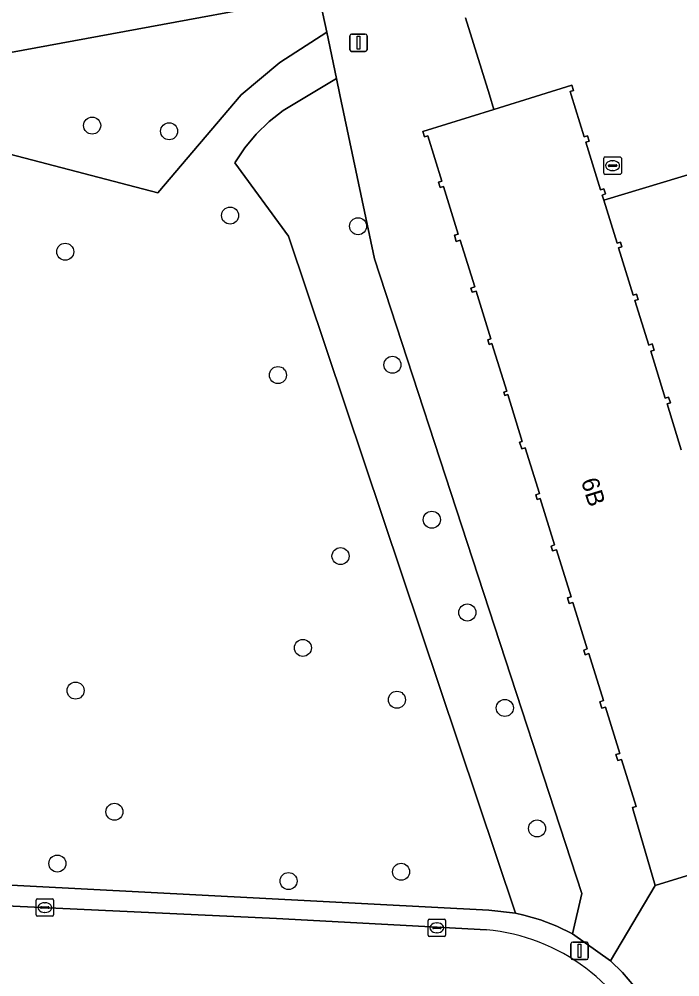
# Model space of a CAD drawing. Extents: x 161248 to 161848, y 384871 to 385383.
# Drawn here: x 161411.8 to 161449.7, y 384949.3 to 385004.4 of the extents above; entities that cross this region are included whole.
import ezdxf

# ---------------------------------------------------------------- set-up
doc = ezdxf.new("R2010")
doc.units = 0
for name, color, linetype in [('IMGEO_Boom', 7, 'Continuous'), ('IMGEO_Erf', 7, 'Continuous'), ('IMGEO_Groenvoorziening', 7, 'Continuous'), ('IMGEO_Hek', 7, 'Continuous'), ('IMGEO_Kolk', 7, 'Continuous'), ('IMGEO_Lichtmast', 7, 'Continuous'), ('IMGEO_Pand', 7, 'Continuous'), ('IMGEO_Pand_nummerreeks', 7, 'Continuous'), ('IMGEO_Rijbaan_lokaal_open', 7, 'Continuous'), ('IMGEO_Rioolput', 7, 'Continuous'), ('IMGEO_Voetpad_open', 7, 'Continuous')]:
    doc.layers.add(name, color=color, linetype=linetype)

msp = doc.modelspace()

# ---------------------------------------------------------------- linework, layer by layer
at = {"layer": 'IMGEO_Boom'}
for centre in [(161415.979, 384998.236), (161420.399, 384997.91), (161423.899, 384993.064), (161431.249, 384992.453), (161414.431, 384990.989), (161433.223, 384984.489), (161426.651, 384983.899), (161435.488, 384975.586), (161430.243, 384973.495), (161437.527, 384970.251), (161428.081, 384968.214), (161415.029, 384965.761), (161433.486, 384965.238), (161439.681, 384964.763), (161417.258, 384958.8), (161441.529, 384957.841), (161413.98, 384955.819), (161433.72, 384955.346), (161427.258, 384954.817)]:
    msp.add_circle(centre, 0.489, dxfattribs=at)
at = {"layer": 'IMGEO_Erf'}
msp.add_lwpolyline([(161417, 385055.584), (161373.417, 385041.421), (161374.342, 385036.357), (161375.419, 385030.464), (161376.296, 385025.659), (161377.093, 385021.299), (161377.39, 385019.671), (161380.984, 385000), (161381.538, 384996.968), (161428.963, 385005.723), (161422.894, 385029.848), (161421.184, 385036.607), (161421.765, 385036.754)], close=True, dxfattribs=at)
msp.add_lwpolyline([(161429.001, 385005.73), (161429.448, 385003.612), (161430.009, 385000.952), (161430.209, 385000), (161432.194, 384990.572), (161444.094, 384954.097), (161443.567, 384951.787), (161445.755, 384950.228), (161448.319, 384954.566), (161447.068, 384958.835), (161447.004, 384959.044), (161447.214, 384959.109), (161446.379, 384961.802), (161446.171, 384961.737), (161446.063, 384962.086), (161446.283, 384962.154), (161445.458, 384964.813), (161445.252, 384964.749), (161445.135, 384965.125), (161445.344, 384965.19), (161444.507, 384967.888), (161444.298, 384967.824), (161444.214, 384968.094), (161444.416, 384968.157), (161443.588, 384970.826), (161443.38, 384970.762), (161443.279, 384971.086), (161443.488, 384971.151), (161442.648, 384973.858), (161442.423, 384973.789), (161442.337, 384974.068), (161442.538, 384974.131), (161441.709, 384976.801), (161441.538, 384976.748), (161441.453, 384977.019), (161441.665, 384977.085), (161440.848, 384979.718), (161440.649, 384979.656), (161440.53, 384980.038), (161440.684, 384980.086), (161439.847, 384982.78), (161439.683, 384982.729), (161439.623, 384982.922), (161439.788, 384982.974), (161438.941, 384985.704), (161438.78, 384985.654), (161438.696, 384985.924), (161438.88, 384985.981), (161438.029, 384988.724), (161437.809, 384988.656), (161437.735, 384988.893), (161437.951, 384988.96), (161437.116, 384991.649), (161436.892, 384991.579), (161436.781, 384991.936), (161437.006, 384992.006), (161436.159, 384994.739), (161435.967, 384994.68), (161435.873, 384994.985), (161436.064, 384995.044), (161435.254, 384997.653), (161435.064, 384997.593), (161434.969, 384997.898), (161439.058, 384999.168), (161438.8, 385000), (161437.426, 385004.427)], dxfattribs=at)
at = {"layer": 'IMGEO_Groenvoorziening'}
for points in [[(161424.534, 385000), (161426.767, 385001.869), (161429.448, 385003.612), (161429.001, 385005.73), (161428.963, 385005.723), (161381.538, 384996.968), (161378.531, 384996.444), (161381.658, 384978.992), (161385.169, 384955.944), (161385.699, 384955.916), (161382.254, 384992.314), (161382.704, 384992.395), (161409.099, 384997.144), (161419.747, 384994.367)], [(161426.767, 385001.869), (161424.534, 385000), (161419.747, 384994.367), (161409.099, 384997.144), (161382.704, 384992.395), (161382.254, 384992.314), (161385.699, 384955.916), (161438.755, 384953.144), (161440.288, 384952.96), (161427.248, 384991.885), (161424.179, 384996.091), (161424.75, 384996.95), (161425.408, 384997.745), (161426.145, 384998.467), (161426.954, 384999.107), (161430.009, 385000.952), (161429.448, 385003.612)], [(161443.567, 384951.787), (161444.094, 384954.097), (161432.194, 384990.572), (161430.209, 385000), (161430.009, 385000.952), (161426.954, 384999.107), (161426.145, 384998.467), (161425.408, 384997.745), (161424.75, 384996.95), (161424.179, 384996.091), (161427.248, 384991.885), (161440.288, 384952.96), (161440.771, 384952.857), (161441.734, 384952.584), (161442.668, 384952.227)], [(161456.306, 384927.519), (161456.058, 384928.282), (161468.671, 384932.496), (161460.725, 384958.4), (161453.097, 384956.043), (161448.319, 384954.566), (161445.755, 384950.228), (161446.432, 384949.557), (161447.081, 384948.789), (161447.66, 384947.966), (161448.163, 384947.095), (161448.585, 384946.183), (161448.925, 384945.236), (161454.217, 384928.071), (161455.63, 384928.386), (161455.957, 384927.409)]]:
    msp.add_lwpolyline(points, close=True, dxfattribs=at)
at = {"layer": 'IMGEO_Hek'}
msp.add_lwpolyline([(161452.034, 384995.958), (161445.368, 384993.944)], dxfattribs=at)
at = {"layer": 'IMGEO_Kolk'}
for p, q in [((161412.759, 384952.865), (161412.759, 384953.717)), ((161412.834, 384953.791), (161413.686, 384953.791)), ((161413.76, 384953.717), (161413.76, 384952.865)), ((161413.018, 384953.285), (161413.018, 384953.297)), ((161413.456, 384953.248), (161413.058, 384953.248)), ((161413.061, 384953.334), (161413.459, 384953.334)), ((161413.247, 384953.571), (161413.272, 384953.571)), ((161413.502, 384953.297), (161413.502, 384953.285)), ((161413.686, 384952.791), (161412.834, 384952.791)), ((161413.27, 384953.011), (161413.245, 384953.011)), ((161435.352, 384952.625), (161436.204, 384952.625)), ((161435.277, 384951.699), (161435.277, 384952.551)), ((161435.536, 384952.119), (161435.536, 384952.131)), ((161435.974, 384952.082), (161435.576, 384952.082)), ((161435.579, 384952.168), (161435.977, 384952.168)), ((161435.765, 384952.405), (161435.79, 384952.405)), ((161436.02, 384952.131), (161436.02, 384952.119)), ((161436.278, 384952.551), (161436.278, 384951.699)), ((161436.204, 384951.625), (161435.352, 384951.625)), ((161435.788, 384951.845), (161435.763, 384951.845))]:
    msp.add_line(p, q, dxfattribs=at)
for points in [[(161412.759, 384952.865), (161412.759, 384953.717)], [(161412.834, 384953.791), (161413.686, 384953.791)], [(161413.76, 384953.717), (161413.76, 384952.865)], [(161413.686, 384952.791), (161412.834, 384952.791)], [(161435.352, 384952.625), (161436.204, 384952.625)], [(161435.277, 384951.699), (161435.277, 384952.551)], [(161436.278, 384952.551), (161436.278, 384951.699)], [(161436.204, 384951.625), (161435.352, 384951.625)]]:
    msp.add_lwpolyline(points, dxfattribs=at)
for centre, radius, start, end in [((161412.836, 384953.715), 0.0765, 91.552, 178.448), ((161412.836, 384953.715), 0.0765, 91.552, 178.448), ((161413.684, 384953.715), 0.0765, 1.552, 88.448), ((161413.684, 384953.715), 0.0765, 1.552, 88.448), ((161413.058, 384953.294), 0.0403, 85.8775, 175.7526), ((161413.055, 384953.284), 0.0366, 178.938, 274.7102), ((161413.459, 384953.291), 0.043, 264.8664, 352.4533), ((161413.463, 384953.296), 0.0386, 1.7309, 96.639), ((161412.836, 384952.867), 0.0765, 181.552, 268.448), ((161412.836, 384952.867), 0.0765, 181.552, 268.448), ((161413.684, 384952.867), 0.0765, 271.552, 358.448), ((161413.684, 384952.867), 0.0765, 271.552, 358.448), ((161435.354, 384952.549), 0.0765, 91.552, 178.448), ((161435.354, 384952.549), 0.0765, 91.552, 178.448), ((161436.202, 384952.549), 0.0765, 1.552, 88.448), ((161436.202, 384952.549), 0.0765, 1.552, 88.448), ((161435.576, 384952.128), 0.0403, 85.8775, 175.7526), ((161435.573, 384952.118), 0.0366, 178.938, 274.7102), ((161435.977, 384952.125), 0.043, 264.8664, 352.4533), ((161435.981, 384952.13), 0.0386, 1.7309, 96.639), ((161435.354, 384951.701), 0.0765, 181.552, 268.448), ((161435.354, 384951.701), 0.0765, 181.552, 268.448), ((161436.202, 384951.701), 0.0765, 271.552, 358.448), ((161436.202, 384951.701), 0.0765, 271.552, 358.448)]:
    msp.add_arc(centre, radius, start, end, dxfattribs=at)
for centre, major_axis, ratio, start_param, end_param in [((161413.246, 384953.291), (-0.387, 0.002), 0.722429, 4.712389, 7.853982), ((161413.271, 384953.291), (-0.39, 0.002), 0.717154, 1.570796, 4.712389), ((161435.764, 384952.125), (-0.387, 0.002), 0.722429, 4.712389, 7.853982), ((161435.789, 384952.125), (-0.39, 0.002), 0.717154, 1.570796, 4.712389)]:
    msp.add_ellipse(centre, major_axis=major_axis, ratio=ratio, start_param=start_param, end_param=end_param, dxfattribs=at)
at = {"layer": 'IMGEO_Lichtmast'}
for p, q in [((161430.778, 385002.598), (161430.778, 385003.398)), ((161430.778, 385003.398), (161430.778, 385002.598)), ((161430.878, 385003.498), (161431.668, 385003.498)), ((161431.668, 385003.498), (161430.878, 385003.498)), ((161431.768, 385003.398), (161431.768, 385002.598)), ((161431.768, 385002.598), (161431.768, 385003.398)), ((161431.668, 385002.498), (161430.878, 385002.498)), ((161430.878, 385002.498), (161431.668, 385002.498)), ((161443.48, 384950.404), (161443.48, 384951.204)), ((161443.48, 384951.204), (161443.48, 384950.404)), ((161443.58, 384951.304), (161444.37, 384951.304)), ((161444.37, 384951.304), (161443.58, 384951.304)), ((161444.47, 384951.204), (161444.47, 384950.404)), ((161444.47, 384950.404), (161444.47, 384951.204)), ((161444.37, 384950.304), (161443.58, 384950.304)), ((161443.58, 384950.304), (161444.37, 384950.304))]:
    msp.add_line(p, q, dxfattribs=at)
for points in [[(161431.198, 385003.373), (161431.348, 385003.373), (161431.348, 385002.623), (161431.198, 385002.623), (161431.198, 385003.373)], [(161443.9, 384951.179), (161444.05, 384951.179), (161444.05, 384950.429), (161443.9, 384950.429), (161443.9, 384951.179)]]:
    msp.add_lwpolyline(points, dxfattribs=at)
for centre, start, end in [((161430.878, 385003.398), 90, 180), ((161430.878, 385003.398), 90, 180), ((161431.668, 385003.398), 0, 90), ((161431.668, 385003.398), 360, 90), ((161430.878, 385002.598), 180, 270), ((161430.878, 385002.598), 180, 270), ((161431.668, 385002.598), 270, 0), ((161431.668, 385002.598), 270, 0), ((161443.58, 384951.204), 90, 180), ((161443.58, 384951.204), 90, 180), ((161444.37, 384951.204), 0, 90), ((161444.37, 384951.204), 360, 90), ((161443.58, 384950.404), 180, 270), ((161443.58, 384950.404), 180, 270), ((161444.37, 384950.404), 270, 0), ((161444.37, 384950.404), 270, 0)]:
    msp.add_arc(centre, 0.1, start, end, dxfattribs=at)
at = {"layer": 'IMGEO_Pand'}
msp.add_lwpolyline([(161449.815, 384979.605), (161448.998, 384982.236), (161449.19, 384982.296), (161449.085, 384982.632), (161448.895, 384982.573), (161448.06, 384985.263), (161448.25, 384985.323), (161448.138, 384985.684), (161447.948, 384985.625), (161447.156, 384988.179), (161447.346, 384988.238), (161447.25, 384988.547), (161447.06, 384988.488), (161446.217, 384991.205), (161446.407, 384991.266), (161446.32, 384991.544), (161446.13, 384991.487), (161445.368, 384993.944), (161445.274, 384994.246), (161445.464, 384994.309), (161445.372, 384994.603), (161445.182, 384994.544), (161444.334, 384997.277), (161444.53, 384997.338), (161444.429, 384997.642), (161444.239, 384997.582), (161443.49, 385000), (161443.431, 385000.19), (161443.622, 385000.25), (161443.527, 385000.555), (161441.739, 385000), (161439.058, 384999.168), (161434.969, 384997.898), (161435.064, 384997.593), (161435.254, 384997.653), (161436.064, 384995.044), (161435.873, 384994.985), (161435.967, 384994.68), (161436.159, 384994.739), (161437.006, 384992.006), (161436.781, 384991.936), (161436.892, 384991.579), (161437.116, 384991.649), (161437.951, 384988.96), (161437.735, 384988.893), (161437.809, 384988.656), (161438.029, 384988.724), (161438.88, 384985.981), (161438.696, 384985.924), (161438.78, 384985.654), (161438.941, 384985.704), (161439.788, 384982.974), (161439.623, 384982.922), (161439.683, 384982.729), (161439.847, 384982.78), (161440.684, 384980.086), (161440.53, 384980.038), (161440.649, 384979.656), (161440.848, 384979.718), (161441.665, 384977.085), (161441.453, 384977.019), (161441.538, 384976.748), (161441.709, 384976.801), (161442.538, 384974.131), (161442.337, 384974.068), (161442.423, 384973.789), (161442.648, 384973.858), (161443.488, 384971.151), (161443.279, 384971.086), (161443.38, 384970.762), (161443.588, 384970.826), (161444.416, 384968.157), (161444.214, 384968.094), (161444.298, 384967.824), (161444.507, 384967.888), (161445.344, 384965.19), (161445.135, 384965.125), (161445.252, 384964.749), (161445.458, 384964.813), (161446.283, 384962.154), (161446.063, 384962.086), (161446.171, 384961.737), (161446.379, 384961.802), (161447.214, 384959.109), (161447.004, 384959.044), (161447.068, 384958.835), (161448.319, 384954.566), (161453.097, 384956.043)], dxfattribs=at)
at = {"layer": 'IMGEO_Rijbaan_lokaal_open'}
for points in [[(161437.426, 385004.427), (161438.8, 385000), (161439.058, 384999.168), (161441.739, 385000), (161443.527, 385000.555), (161443.622, 385000.25), (161443.431, 385000.19), (161443.49, 385000), (161444.239, 384997.582), (161444.429, 384997.642), (161444.53, 384997.338), (161444.334, 384997.277), (161445.182, 384994.544), (161445.372, 384994.603), (161445.464, 384994.309), (161445.274, 384994.246), (161445.368, 384993.944), (161452.034, 384995.958)], [(161452.034, 384995.958), (161445.368, 384993.944), (161446.13, 384991.487), (161446.32, 384991.544), (161446.407, 384991.266), (161446.217, 384991.205), (161447.06, 384988.488), (161447.25, 384988.547), (161447.346, 384988.238), (161447.156, 384988.179), (161447.948, 384985.625), (161448.138, 384985.684), (161448.25, 384985.323), (161448.06, 384985.263), (161448.895, 384982.573), (161449.085, 384982.632), (161449.19, 384982.296), (161448.998, 384982.236), (161449.815, 384979.605)], [(161438.622, 384952.015), (161426.573, 384952.665), (161402.419, 384953.798)]]:
    msp.add_lwpolyline(points, dxfattribs=at)
msp.add_arc((161437.605, 384940.914), 11.147, 21.1103, 84.764, dxfattribs=at)
at = {"layer": 'IMGEO_Rioolput'}
for p, q in [((161445.371, 384995.508), (161445.371, 384996.36)), ((161445.446, 384996.434), (161446.298, 384996.434)), ((161445.859, 384996.214), (161445.884, 384996.214)), ((161446.372, 384996.36), (161446.372, 384995.508)), ((161445.63, 384995.928), (161445.63, 384995.94)), ((161446.068, 384995.891), (161445.67, 384995.891)), ((161445.673, 384995.977), (161446.071, 384995.977)), ((161445.882, 384995.654), (161445.857, 384995.654)), ((161446.114, 384995.94), (161446.114, 384995.928)), ((161446.298, 384995.434), (161445.446, 384995.434))]:
    msp.add_line(p, q, dxfattribs=at)
for points in [[(161445.371, 384995.508), (161445.371, 384996.36)], [(161445.446, 384996.434), (161446.298, 384996.434)], [(161446.372, 384996.36), (161446.372, 384995.508)], [(161446.298, 384995.434), (161445.446, 384995.434)]]:
    msp.add_lwpolyline(points, dxfattribs=at)
for centre, radius, start, end in [((161445.448, 384996.358), 0.0765, 91.552, 178.448), ((161445.448, 384996.358), 0.0765, 91.552, 178.448), ((161446.296, 384996.358), 0.0765, 1.552, 88.448), ((161446.296, 384996.358), 0.0765, 1.552, 88.448), ((161445.67, 384995.937), 0.0403, 85.8775, 175.7526), ((161445.667, 384995.927), 0.0366, 178.938, 274.7102), ((161446.071, 384995.934), 0.043, 264.8664, 352.4533), ((161446.075, 384995.939), 0.0386, 1.7309, 96.639), ((161445.448, 384995.51), 0.0765, 181.552, 268.448), ((161445.448, 384995.51), 0.0765, 181.552, 268.448), ((161446.296, 384995.51), 0.0765, 271.552, 358.448), ((161446.296, 384995.51), 0.0765, 271.552, 358.448)]:
    msp.add_arc(centre, radius, start, end, dxfattribs=at)
for centre, major_axis, ratio, start_param, end_param in [((161445.858, 384995.934), (-0.387, 0.002), 0.722429, 4.712389, 7.853982), ((161445.883, 384995.934), (-0.39, 0.002), 0.717154, 1.570796, 4.712389)]:
    msp.add_ellipse(centre, major_axis=major_axis, ratio=ratio, start_param=start_param, end_param=end_param, dxfattribs=at)
at = {"layer": 'IMGEO_Voetpad_open'}
for points in [[(161447.081, 384948.789), (161446.432, 384949.557), (161445.755, 384950.228), (161443.567, 384951.787), (161442.668, 384952.227), (161441.734, 384952.584), (161440.771, 384952.857), (161440.288, 384952.96), (161438.755, 384953.144), (161385.699, 384955.916)], [(161402.419, 384953.798), (161426.573, 384952.665), (161438.622, 384952.015)]]:
    msp.add_lwpolyline(points, dxfattribs=at)
msp.add_arc((161437.605, 384940.914), 11.147, 21.1103, 84.764, dxfattribs=at)

# ---------------------------------------------------------------- texts
at = {"layer": 'IMGEO_Pand_nummerreeks'}
msp.add_text('6B', height=1, rotation=287.2377, dxfattribs=at).set_placement((161444.046, 384977.819))

doc.saveas('drawing.dxf')
